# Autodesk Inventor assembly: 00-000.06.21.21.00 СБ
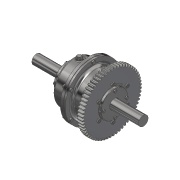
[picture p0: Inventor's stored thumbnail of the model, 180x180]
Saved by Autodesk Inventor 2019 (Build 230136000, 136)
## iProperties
Created: 2019-01
Part Number: 00-000.06.21.21.00 СБ
Document SubType Name: Assembly
Designer: m.vorobev
Author: m.vorobev
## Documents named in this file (31)
- C:\Users\m.vorobev.TRINITY\Documents\Inventor\00-000.06.21.21.00\00-000.06.21.21.00 СБ.iam
- C:\Users\m.vorobev.TRINITY\Documents\Inventor\00-000.06.21.21.00\00-000.06.21.21.10.ipt
- C:\Users\m.vorobev.TRINITY\Documents\Inventor\00-000.06.21.21.00\00-000.06.21.21.01.ipt
- C:\Users\m.vorobev.TRINITY\Documents\Inventor\00-000.06.21.21.00\00-000.06.21.21.02.ipt
- C:\Users\m.vorobev.TRINITY\Documents\Inventor\00-000.06.21.21.00\Content Center Files\en-US\Bolt GOST 7798-78\Bolt  M10-6g×35(S16) GOST 7798-70.ipt
- C:\Users\m.vorobev.TRINITY\Documents\Inventor\00-000.06.21.21.00\Content Center Files\en-US\GOST 6402-70\Washer  10 L GOST 6402-70.ipt
- C:\Users\m.vorobev.TRINITY\Documents\Inventor\00-000.06.21.21.00\Content Center Files\en-US\GOST 5916-70\Nut M10-6H GOST 5916-70.ipt
- C:\Users\m.vorobev.TRINITY\Documents\Inventor\00-000.06.21.21.00\00-000.06.21.21.15.ipt
- C:\Users\m.vorobev.TRINITY\Documents\Inventor\00-000.06.21.21.00\00-000.06.21.21.05.ipt
- C:\Users\m.vorobev.TRINITY\Documents\Inventor\00-000.06.21.21.00\Key 2-36x20x100 GOST 23360-78.ipt
- C:\Users\m.vorobev.TRINITY\Documents\Inventor\00-000.06.21.21.00\Content Center Files\en-US\Stud GOST 22034-76\Stud M10-6g×45 GOST 22034-76.ipt
- C:\Users\m.vorobev.TRINITY\Documents\Inventor\00-000.06.21.21.00\00-000.06.21.21.07.ipt
- C:\Users\m.vorobev.TRINITY\Documents\Inventor\00-000.06.21.21.00\00-000.06.21.21.11,12,13\00-000.06.21.21.12.ipt
- C:\Users\m.vorobev.TRINITY\Documents\Inventor\00-000.06.21.21.00\00-000.06.21.21.11,12,13.ipt
- C:\Users\m.vorobev.TRINITY\Documents\Inventor\00-000.06.21.21.00\00-000.06.21.21.03.ipt
- C:\Users\m.vorobev.TRINITY\Documents\Inventor\00-000.06.21.21.00\00-000.06.21.21.04.ipt
- C:\Users\m.vorobev.TRINITY\Documents\Inventor\00-000.06.21.21.00\Key 2-12x8x28 GOST 23360-78.ipt
- C:\Users\m.vorobev.TRINITY\Documents\Inventor\00-000.06.21.21.00\Content Center Files\en-US\Nut GOST 12460-67\Nut 7003-0141 GOST 12460-67.ipt
- C:\Users\m.vorobev.TRINITY\Documents\Inventor\00-000.06.21.21.00\00-000.06.21.21.11,12,13\00-000.06.21.21.11.ipt
- C:\Users\m.vorobev.TRINITY\Documents\Inventor\00-000.06.21.21.00\Content Center Files\en-US\GOST 8338-75\Bearing 309 GOST 8338-75.ipt
- C:\Users\m.vorobev.TRINITY\Documents\Inventor\00-000.06.21.21.00\00-000.06.21.21.11,12,13\00-000.06.21.21.13.ipt
- C:\Users\m.vorobev.TRINITY\Documents\Inventor\00-000.06.21.21.00\00-000.06.21.21.08,09\00-000.06.21.21.08.ipt
- C:\Users\m.vorobev.TRINITY\Documents\Inventor\00-000.06.21.21.00\00-000.06.21.21.08,09.ipt
- C:\Users\m.vorobev.TRINITY\Documents\Inventor\00-000.06.21.21.00\00-000.06.21.21.08,09\00-000.06.21.21.09.ipt
- C:\Users\m.vorobev.TRINITY\Documents\Inventor\00-000.06.21.21.00\00-000.06.21.21.29.ipt
- C:\Users\m.vorobev.TRINITY\Documents\Inventor\00-000.06.21.21.00\Content Center Files\en-US\GOST 6402-70\Washer  8 L GOST 6402-70.ipt
- C:\Users\m.vorobev.TRINITY\Documents\Inventor\00-000.06.21.21.00\Content Center Files\en-US\Bolt GOST 7798-78\Bolt  M8-6g×35(S13) GOST 7798-70.ipt
- C:\Users\m.vorobev.TRINITY\Documents\Inventor\00-000.06.21.21.00\00-000.06.21.21.06.ipt
- C:\Users\m.vorobev.TRINITY\Documents\Inventor\00-000.06.21.21.00\00-000.06.21.21.17.ipt
- C:\Users\m.vorobev.TRINITY\Documents\Inventor\00-000.06.21.21.00\00-000.06.21.21.16.ipt
- C:\Users\m.vorobev.TRINITY\Documents\Inventor\00-000.06.21.21.00\00-000.06.21.21.14.ipt
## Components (104 placed, 28 different names)
1. 00-000.06.21.21.10:1 — Mate:4, Mate:5, Mate:6, Mate:7, Mate:8, Mate:16, Mate:23
2. 00-000.06.21.21.01:1 — Mate:19, Insert:70, Mate:21, Insert:90, Mate:22, Insert:93, Mate:24, Insert:95
3. 00-000.06.21.21.02:1 — Insert:19, Mate:1, Mate:2, Mate:3, Insert:20, Insert:21, Mate:18, Insert:53, Insert:71, Mate:20, Mate:23, Insert:95
4. 00-000.06.21.21.15:1 — Insert:19
5. 00-000.06.21.21.05:1 — Angle:1, Insert:21
6. Key 2-36x20x100 GOST 23360-78:1 — Mate:1, Mate:2, Mate:3, Angle:1
7. 00-000.06.21.21.07:1 — Mate:14, Insert:44, Mate:15, Mate:17, Insert:45, Insert:46, Insert:47, Insert:48, Mate:24, Drive
8. 00-000.06.21.21.12:1 — Insert:38, Insert:44
9. 00-000.06.21.21.12:2 — Insert:39, Insert:47
10. 00-000.06.21.21.12:3 — Insert:41, Insert:46
11. 00-000.06.21.21.12:4 — Insert:40, Insert:45
12. 00-000.06.21.21.03:1 — Insert:38, Rotation:1
13. 00-000.06.21.21.03:2 — Insert:39, Rotation:2
14. 00-000.06.21.21.03:3 — Insert:40, Rotation:4
15. 00-000.06.21.21.03:4 — Insert:41, Rotation:3, Rotation:5
16. 00-000.06.21.21.04:1 — Mate:7, Angle:2, Mate:8, Insert:42, Mate:15, Rotation:1, Rotation:2, Rotation:3, Rotation:4, Insert:49
17. Key 2-12x8x28 GOST 23360-78:1 — Mate:4, Mate:5, Mate:6, Angle:2
18. 00-000.06.21.21.10:2 — Mate:16, Mate:22
19. 00-000.06.21.21.04:2 — Mate:17, Rotation:5, Insert:50
20. Key 2-12x8x28 GOST 23360-78:2
21. 00-000.06.21.21.11:5 — Insert:48
22. 00-000.06.21.21.13:6 — Insert:49
23. 00-000.06.21.21.13:7 — Insert:50
24. 00-000.06.21.21.08:1 — Insert:51, Mate:18, Insert:53, Insert:80
25. 00-000.06.21.21.09:2 — Insert:52, Insert:63, Insert:67, Insert:68, Insert:69, Mate:19, Insert:70, Insert:89, Insert:91
26. 00-000.06.21.21.29:1 — Insert:51
27. 00-000.06.21.21.29:2 — Insert:52
28. 00-000.06.21.21.06:1 — Insert:71, Mate:20, Insert:76, Insert:77, Insert:78, Insert:79
29. 00-000.06.21.21.06:2 — Mate:21, Insert:90
30. 00-000.06.21.21.17:1 — Insert:93, Insert:94
31. 00-000.06.21.21.16:1 — Insert:91
32. 00-000.06.21.21.14:1 — Insert:94
33. Bolt GOST 7798-70 M10-6g×35(S16):1
34. Bolt GOST 7798-70 M10-6g×35(S16):2
35. Bolt GOST 7798-70 M10-6g×35(S16):3
36. Bolt GOST 7798-70 M10-6g×35(S16):4
37. Bolt GOST 7798-70 M10-6g×35(S16):5
38. Bolt GOST 7798-70 M10-6g×35(S16):6
39. Washer GOST 6402-70 10 L:1
40. Washer GOST 6402-70 10 L:2
41. Washer GOST 6402-70 10 L:3
42. Washer GOST 6402-70 10 L:4
43. Washer GOST 6402-70 10 L:5
44. Washer GOST 6402-70 10 L:6
45. Nut GOST 5916-70 M10:1
46. Nut GOST 5916-70 M10:2
47. Nut GOST 5916-70 M10:3
48. Nut GOST 5916-70 M10:4
49. Nut GOST 5916-70 M10:5
50. Nut GOST 5916-70 M10:6
51. Washer GOST 6402-70 10 L:7 — Insert:28
52. Washer GOST 6402-70 10 L:8 — Insert:33
53. Washer GOST 6402-70 10 L:9 — Insert:32
54. Washer GOST 6402-70 10 L:10 — Insert:31
55. Washer GOST 6402-70 10 L:11 — Insert:30
56. Washer GOST 6402-70 10 L:12 — Insert:29
57. Nut GOST 5916-70 M10:7 — Insert:28
58. Nut GOST 5916-70 M10:8 — Insert:33
59. Nut GOST 5916-70 M10:9 — Insert:29
60. Nut GOST 5916-70 M10:10 — Insert:30
61. Nut GOST 5916-70 M10:11 — Insert:31
62. Nut GOST 5916-70 M10:12 — Insert:32
63. Nut GOST 12460-67 7003-0141:1 — Insert:42, Mate:14
64. Nut GOST 12460-67 7003-0141:3
65. Bearing GOST 8338-75 309:1 — Insert:89
66. Washer GOST 6402-70 8 L:1
67. Washer GOST 6402-70 8 L:2 — Insert:59
68. Washer GOST 6402-70 8 L:3 — Insert:61
69. Washer GOST 6402-70 8 L:4 — Insert:60
70. Bolt GOST 7798-70 M8-6g×35(S13):1
71. Bolt GOST 7798-70 M8-6g×35(S13):2 — Insert:59
72. Bolt GOST 7798-70 M8-6g×35(S13):3 — Insert:61
73. Bolt GOST 7798-70 M8-6g×35(S13):4 — Insert:60
74. Washer GOST 6402-70 8 L:5 — Insert:63
75. Bolt GOST 7798-70 M8-6g×35(S13):5
76. Washer GOST 6402-70 8 L:6 — Insert:68
77. Bolt GOST 7798-70 M8-6g×35(S13):6
78. Washer GOST 6402-70 8 L:7 — Insert:69
79. Bolt GOST 7798-70 M8-6g×35(S13):7
80. Washer GOST 6402-70 8 L:8 — Insert:67
81. Bolt GOST 7798-70 M8-6g×35(S13):8
82. Washer GOST 6402-70 8 L:9 — Insert:78
83. Bolt GOST 7798-70 M8-6g×35(S13):9
84. Washer GOST 6402-70 8 L:10 — Insert:76
85. Bolt GOST 7798-70 M8-6g×35(S13):10
86. Washer GOST 6402-70 8 L:11 — Insert:79
87. Bolt GOST 7798-70 M8-6g×35(S13):11
88. Washer GOST 6402-70 8 L:12 — Insert:77
89. Bolt GOST 7798-70 M8-6g×35(S13):12
90. Bearing GOST 8338-75 309:2 — Insert:80
91. Washer GOST 6402-70 8 L:13
92. Bolt GOST 7798-70 M8-6g×35(S13):13
93. Washer GOST 6402-70 8 L:14
94. Bolt GOST 7798-70 M8-6g×35(S13):14
95. Washer GOST 6402-70 8 L:15
96. Bolt GOST 7798-70 M8-6g×35(S13):15
97. Washer GOST 6402-70 8 L:16
98. Bolt GOST 7798-70 M8-6g×35(S13):16
99. Stud GOST 22034-76 M10-6g×45:1 — Insert:20
100. Stud GOST 22034-76 M10-6g×45:2
101. Stud GOST 22034-76 M10-6g×45:3
102. Stud GOST 22034-76 M10-6g×45:4
103. Stud GOST 22034-76 M10-6g×45:5
104. Stud GOST 22034-76 M10-6g×45:6
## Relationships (71: Insert 44, Mate 19, RelateRotation 5, Angle 3)
- Insert:19: 00-000.06.21.21.02:1 ↔ 00-000.06.21.21.15:1
- Mate:1: 00-000.06.21.21.02:1 ↔ Key 2-36x20x100 GOST 23360-78:1
- Mate:2: 00-000.06.21.21.02:1 ↔ Key 2-36x20x100 GOST 23360-78:1
- Mate:3: 00-000.06.21.21.02:1 ↔ Key 2-36x20x100 GOST 23360-78:1
- Insert:20: 00-000.06.21.21.02:1 ↔ Stud GOST 22034-76 M10-6g×45:1
- Angle:1: 00-000.06.21.21.05:1 ↔ Key 2-36x20x100 GOST 23360-78:1
- Insert:21: 00-000.06.21.21.02:1 ↔ 00-000.06.21.21.05:1
- Insert:28: Washer GOST 6402-70 10 L:7 ↔ Nut GOST 5916-70 M10:7
- Insert:29: Washer GOST 6402-70 10 L:12 ↔ Nut GOST 5916-70 M10:9
- Insert:30: Washer GOST 6402-70 10 L:11 ↔ Nut GOST 5916-70 M10:10
- Insert:31: Washer GOST 6402-70 10 L:10 ↔ Nut GOST 5916-70 M10:11
- Insert:32: Washer GOST 6402-70 10 L:9 ↔ Nut GOST 5916-70 M10:12
- Insert:33: Washer GOST 6402-70 10 L:8 ↔ Nut GOST 5916-70 M10:8
- Insert:38: 00-000.06.21.21.12:1 ↔ 00-000.06.21.21.03:1
- Insert:39: 00-000.06.21.21.12:2 ↔ 00-000.06.21.21.03:2
- Insert:40: 00-000.06.21.21.12:4 ↔ 00-000.06.21.21.03:3
- Insert:41: 00-000.06.21.21.12:3 ↔ 00-000.06.21.21.03:4
- Mate:4: 00-000.06.21.21.10:1 ↔ Key 2-12x8x28 GOST 23360-78:1
- Mate:5: 00-000.06.21.21.10:1 ↔ Key 2-12x8x28 GOST 23360-78:1
- Mate:6: 00-000.06.21.21.10:1 ↔ Key 2-12x8x28 GOST 23360-78:1
- Mate:7: 00-000.06.21.21.10:1 ↔ 00-000.06.21.21.04:1
- Angle:2: 00-000.06.21.21.04:1 ↔ Key 2-12x8x28 GOST 23360-78:1
- Mate:8: 00-000.06.21.21.10:1 ↔ 00-000.06.21.21.04:1
- Insert:42: 00-000.06.21.21.04:1 ↔ Nut GOST 12460-67 7003-0141:1
- Mate:14: 00-000.06.21.21.07:1 ↔ Nut GOST 12460-67 7003-0141:1
- Insert:44: 00-000.06.21.21.07:1 ↔ 00-000.06.21.21.12:1
- Mate:15: 00-000.06.21.21.07:1 ↔ 00-000.06.21.21.04:1
- Mate:16: 00-000.06.21.21.10:1 ↔ 00-000.06.21.21.10:2
- Mate:17: 00-000.06.21.21.07:1 ↔ 00-000.06.21.21.04:2
- Rotation:1 [RelateRotation]: 00-000.06.21.21.03:1 ↔ 00-000.06.21.21.04:1
- Insert:45: 00-000.06.21.21.07:1 ↔ 00-000.06.21.21.12:4
- Insert:46: 00-000.06.21.21.07:1 ↔ 00-000.06.21.21.12:3
- Insert:47: 00-000.06.21.21.07:1 ↔ 00-000.06.21.21.12:2
- Rotation:2 [RelateRotation]: 00-000.06.21.21.03:2 ↔ 00-000.06.21.21.04:1
- Rotation:3 [RelateRotation]: 00-000.06.21.21.03:4 ↔ 00-000.06.21.21.04:1
- Rotation:4 [RelateRotation]: 00-000.06.21.21.03:3 ↔ 00-000.06.21.21.04:1
- Rotation:5 [RelateRotation]: 00-000.06.21.21.03:4 ↔ 00-000.06.21.21.04:2
- Insert:48: 00-000.06.21.21.07:1 ↔ 00-000.06.21.21.11:5
- Insert:49: 00-000.06.21.21.04:1 ↔ 00-000.06.21.21.13:6
- Insert:50: 00-000.06.21.21.04:2 ↔ 00-000.06.21.21.13:7
- Insert:51: 00-000.06.21.21.08:1 ↔ 00-000.06.21.21.29:1
- Insert:52: 00-000.06.21.21.09:2 ↔ 00-000.06.21.21.29:2
- Mate:18: 00-000.06.21.21.02:1 ↔ 00-000.06.21.21.08:1
- Insert:53: 00-000.06.21.21.02:1 ↔ 00-000.06.21.21.08:1
- Insert:59: Washer GOST 6402-70 8 L:2 ↔ Bolt GOST 7798-70 M8-6g×35(S13):2
- Insert:60: Washer GOST 6402-70 8 L:4 ↔ Bolt GOST 7798-70 M8-6g×35(S13):4
- Insert:61: Washer GOST 6402-70 8 L:3 ↔ Bolt GOST 7798-70 M8-6g×35(S13):3
- Insert:63: 00-000.06.21.21.09:2 ↔ Washer GOST 6402-70 8 L:5
- Insert:67: 00-000.06.21.21.09:2 ↔ Washer GOST 6402-70 8 L:8
- Insert:68: 00-000.06.21.21.09:2 ↔ Washer GOST 6402-70 8 L:6
- Insert:69: 00-000.06.21.21.09:2 ↔ Washer GOST 6402-70 8 L:7
- Mate:19: 00-000.06.21.21.01:1 ↔ 00-000.06.21.21.09:2
- Insert:70: 00-000.06.21.21.01:1 ↔ 00-000.06.21.21.09:2
- Insert:71: 00-000.06.21.21.02:1 ↔ 00-000.06.21.21.06:1
- Mate:20: 00-000.06.21.21.02:1 ↔ 00-000.06.21.21.06:1
- Insert:76: 00-000.06.21.21.06:1 ↔ Washer GOST 6402-70 8 L:10
- Insert:77: 00-000.06.21.21.06:1 ↔ Washer GOST 6402-70 8 L:12
- Insert:78: 00-000.06.21.21.06:1 ↔ Washer GOST 6402-70 8 L:9
- Insert:79: 00-000.06.21.21.06:1 ↔ Washer GOST 6402-70 8 L:11
- Insert:80: 00-000.06.21.21.08:1 ↔ Bearing GOST 8338-75 309:2
- Mate:21: 00-000.06.21.21.01:1 ↔ 00-000.06.21.21.06:2
- Insert:89: 00-000.06.21.21.09:2 ↔ Bearing GOST 8338-75 309:1
- Insert:90: 00-000.06.21.21.01:1 ↔ 00-000.06.21.21.06:2
- Mate:22: 00-000.06.21.21.01:1 ↔ 00-000.06.21.21.10:2
- Mate:23: 00-000.06.21.21.10:1 ↔ 00-000.06.21.21.02:1
- Insert:91: 00-000.06.21.21.09:2 ↔ 00-000.06.21.21.16:1
- Insert:93: 00-000.06.21.21.01:1 ↔ 00-000.06.21.21.17:1
- Insert:94: 00-000.06.21.21.17:1 ↔ 00-000.06.21.21.14:1
- Mate:24: 00-000.06.21.21.01:1 ↔ 00-000.06.21.21.07:1
- Insert:95: 00-000.06.21.21.01:1 ↔ 00-000.06.21.21.02:1
- Drive [Angle]: 00-000.06.21.21.07:1
## Named parameters: d52_d49 = 0, d53_d50 = 0, d54_d51 = 0, d55_d45 = 0, d56_d46 = 0, d57_d47 = 0, d58_d48 = 0, d88_d84 = 0, d90_d88_d84 = 0, d91_d88_d84 = 0, d92_d88_d84 = 0, d100_d84 = 0, d101_d100_d84 = 0, d102_d100_d84 = 0, d103_d100_d84 = 0, d109_d100_d84 = 0, d110_d101_d100_d84 = 0, d111_d102_d100_d84 = 0, d112_d103_d100_d84 = 0, d113_d104 = 0, d114_d105 = 0, d115_d106 = 0, d116_d107 = 0
